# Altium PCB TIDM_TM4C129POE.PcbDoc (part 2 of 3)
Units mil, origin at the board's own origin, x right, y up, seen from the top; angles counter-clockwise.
Board outline 4950 x 3450 mil, 4 copper layers (Component Side, Ground Plane, Power Plane, Solder Side), stack 59.6 mil thick; 159 components, 154 nets, 570 pads, 297 vias.
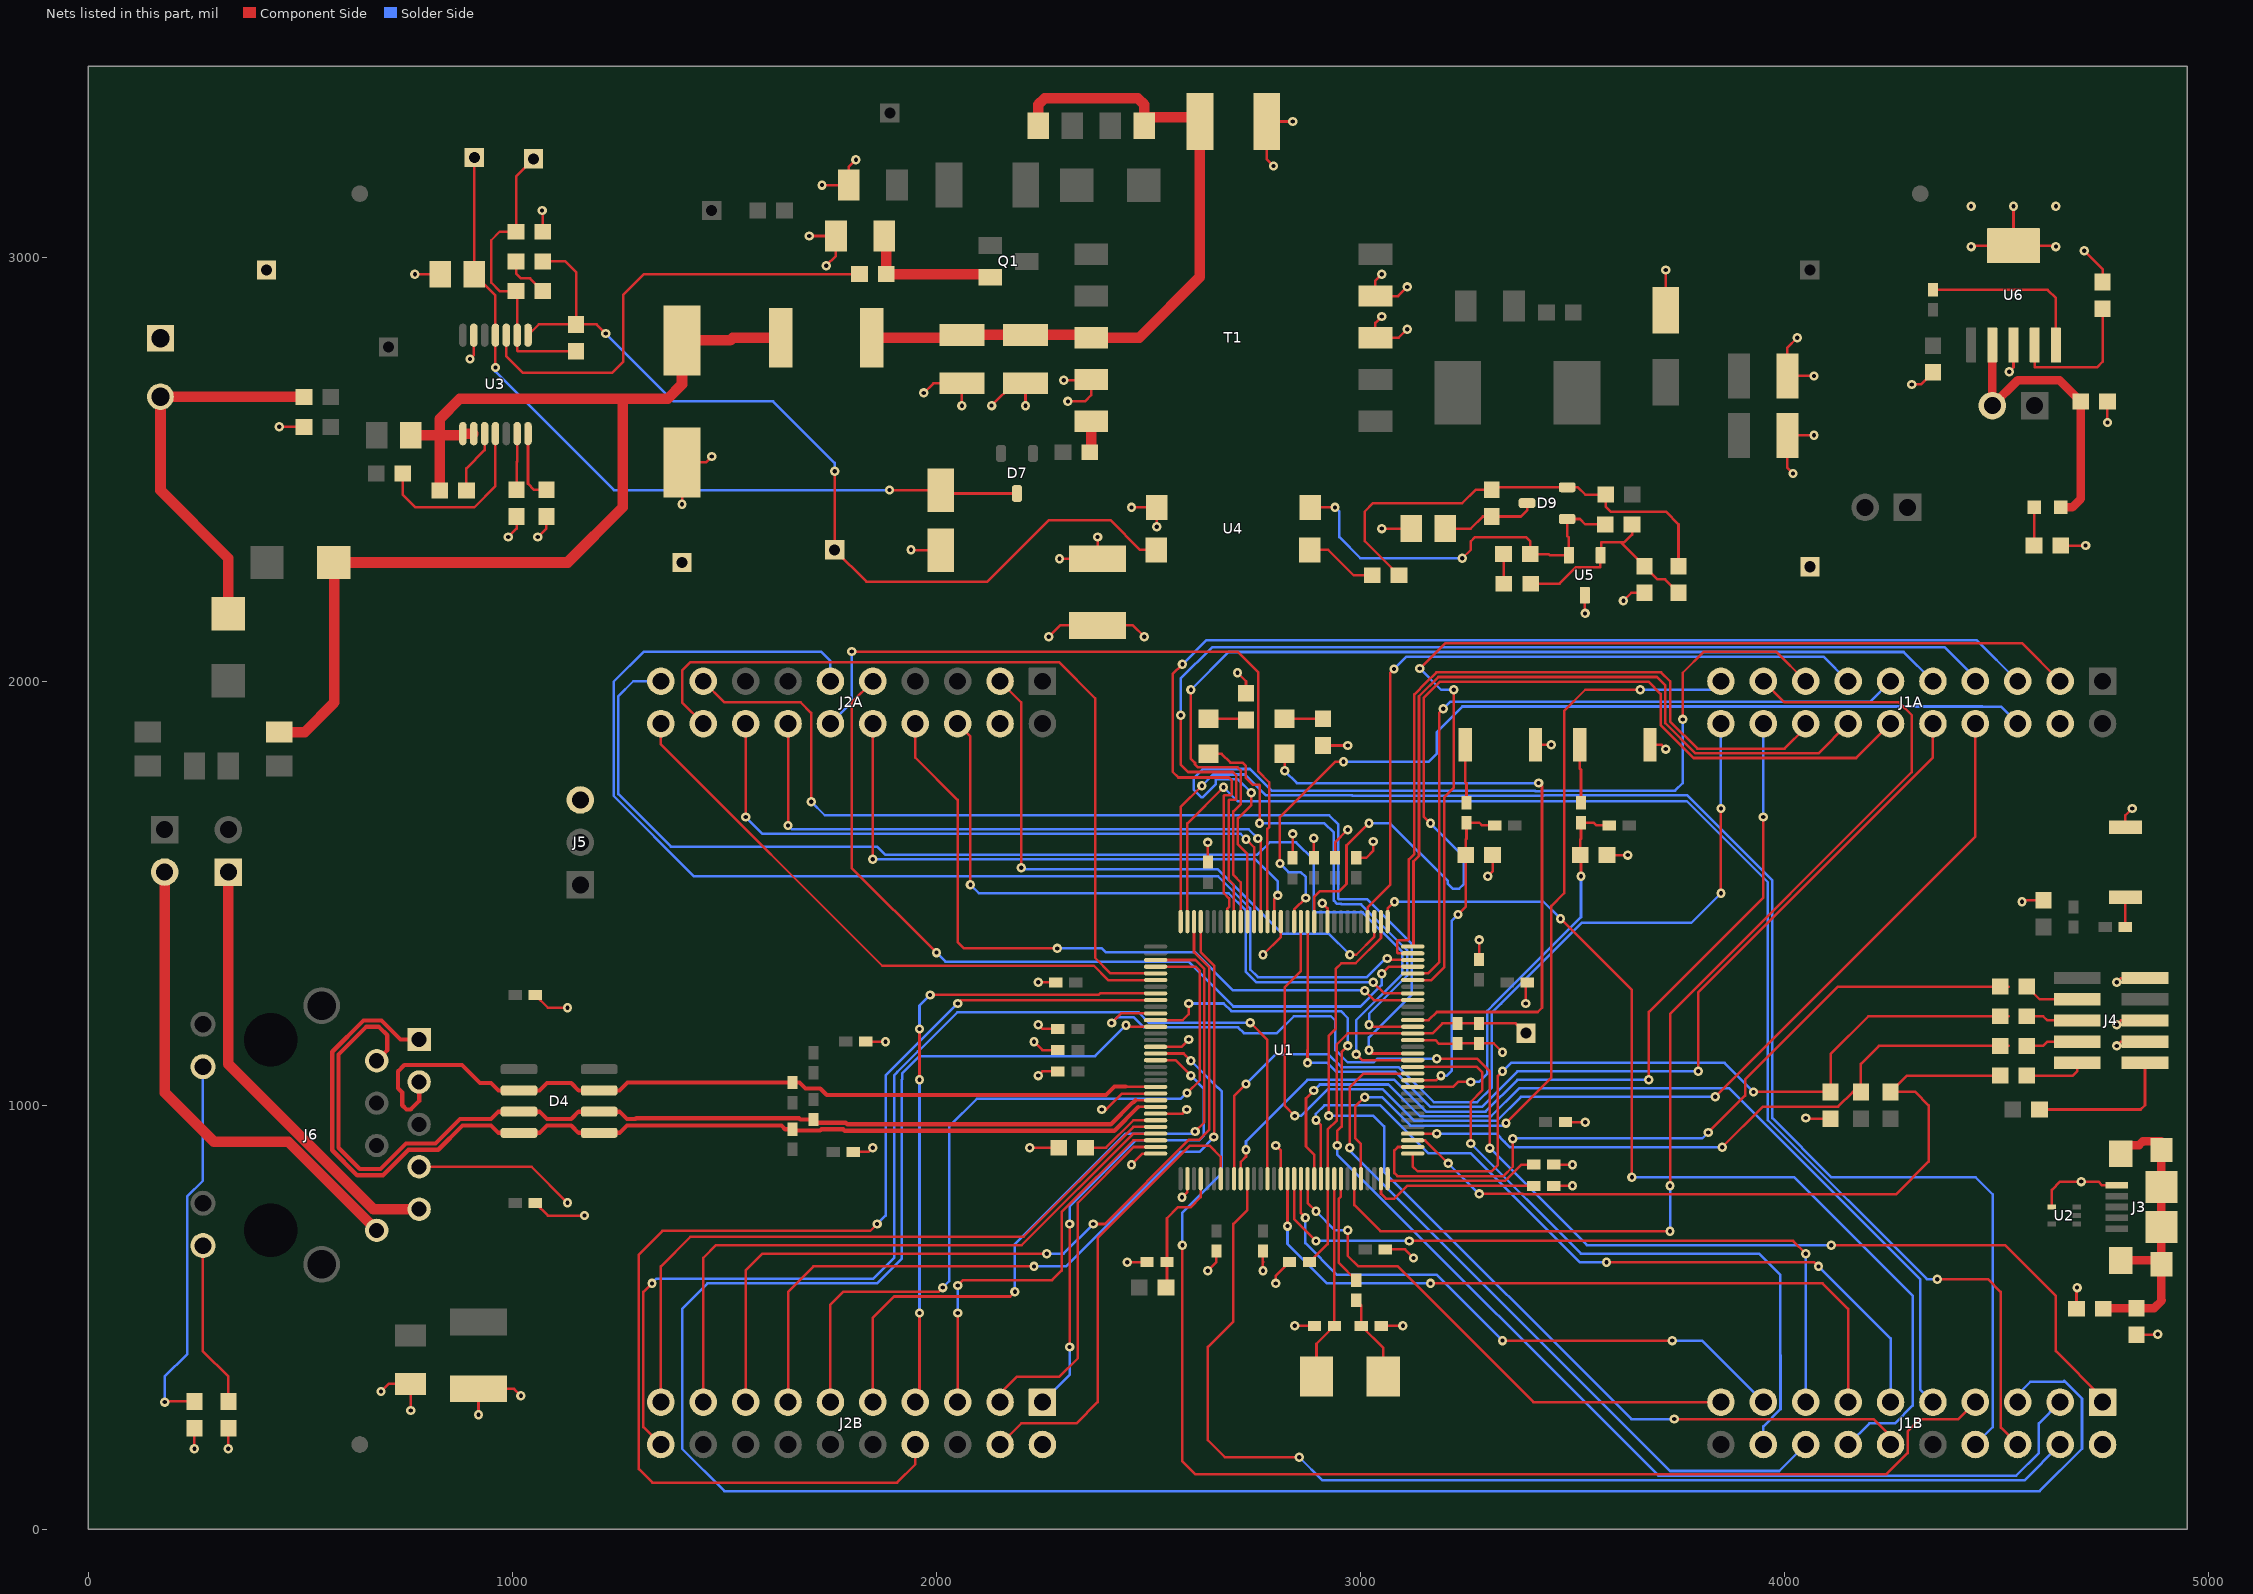
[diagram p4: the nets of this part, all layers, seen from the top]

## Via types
v1: diameter 22, hole 10, Component Side to Solder Side, 297 vias

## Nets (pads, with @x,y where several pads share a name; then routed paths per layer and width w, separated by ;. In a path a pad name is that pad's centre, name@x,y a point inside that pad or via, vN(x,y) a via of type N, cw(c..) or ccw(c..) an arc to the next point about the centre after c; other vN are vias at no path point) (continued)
EPHYRX_P: D4.2 D4.7 J6.3 R22.1 U1.54 | length 2042.3
  Component Side w6: 2446.21,1043.39 U1.54@2516.85,1043.39
  Component Side w10: J6.3@780,1055 780,1010 760,990 750,990 740,1000 740,1030 730,1040 730,1080 745,1095 881.29,1095 923.79,1052.5 949.7,1052.5 967.2,1035 D4.2@1015.51,1035 1063.82,1035 1081.32,1052.5 1138.68,1052.5 1156.18,1035 D4.7@1204.49,1035 1252.8,1035 1271.42,1053.62 R22.1@1660,1053.62 1676.81,1053.62 1691.06,1039.37 1725.96,1039.37 1741.33,1024 2399.81,1024 2420,1044.19 2446.21,1044.19
EPHYTX_N: D4.3 D4.6 J6.2 R23.1 U1.56 | length 2496.1
  Component Side w6: 2469.42,1011.89 U1.56@2516.85,1011.89
  Component Side w10: J6.2@680,1105 705,1130 705,1165 685,1185 655,1185 590,1120 590,900 640,850 688.79,850 748.79,910 818.79,910 876.29,967.5 949.7,967.5 967.2,985 D4.3@1015.51,985 1063.82,985 1081.32,967.5 1138.68,967.5 1156.18,985 D4.6@1204.49,985 1252.8,985 1270.3,967.5 1290,967.5 1291.87,969.37 1675.95,969.37 1678.95,966.38 R23.1@1710,966.38 1717.76,958.62 1786.21,958.62 1789.84,955 2411.16,955 2462.66,1006.5 2464.03,1006.5 2469.42,1011.89
EPHYTX_P: D4.4 D4.5 J6.1 R24.1 U1.57 | length 2558.8
  Component Side w6: 2475.64,996.14 U1.57@2516.85,996.14
  Component Side w10: J6.1@777.35,1155 736.21,1155 691.21,1200 648.79,1200 575,1126.21 575,893.79 633.79,835 695,835 755,895 825,895 882.5,952.5 949.7,952.5 967.2,935 D4.4@1015.51,935 1063.82,935 1081.32,952.5 1138.68,952.5 1156.18,935 D4.5@1204.49,935 1252.8,935 1270.3,952.5 1634.31,952.5 1643.19,943.62 R24.1@1660,943.62 1662.99,940.63 1725.96,940.63 1728.95,943.62 1780,943.62 1783.62,940 2419.49,940 2475.64,996.14
GND: C1.2 C2.2 C3.2 C4.2 C5.2 C6.2 C7.2 C8.2 C9.2 C10.2 C11.2 C12.2 C13.2 C14.2 C15.2 C16.2 C17.2 C18.2 C19.2 C20.2 C21.2 C22.2 C23.2 C24.2 C25.2 C26.2 C27.2 C28.2 C29.2 C30.1 C31.2 C43.1 C44.2 C45.2 C46.2 C47.2 C50.2 C51.2 C52.2 J1A.4 J1B.2 J2A.4 J2B.2 J3.5 J4.3 J4.5 J4.9 J5.3 J6.7 R3.1 R6.2 R7.2 R19.1 R20.1 R25.2 R27.2 R28.2 R29.1 R47.1 R50.1 R51.1 S1.1 S2.1 S3.1 T1.7 T1.8 TP5.1 U1.10 U1.17 U1.48 U1.55 U1.58 U1.64 U1.66 U1.80 U1.114 U2.4 U5.3 U6.3 U6.6 | length 6078.5
  Component Side w6: v1(250,190) R6.2@250,238.5 ; v1(330,190) R7.2@330,238.5 ; v1(690,325) 707.91,342.91 R29.1@760,342.91 v1(760,280) ; J6.7@780,855 1045,855 v1(1130,770) ; v1(920,270) C31.2@920,331.26 1003.74,331.26 v1(1020,315) ; C27.2@1053.62,770 1083.62,740 v1(1170,740) ; C26.2@1053.62,1260 1083.62,1230 v1(1130,1230) ; C29.2@1803.62,890 1840,890 v1(1850,900) ; C28.2@1833.62,1150 v1(1880,1150) ; v1(2220,900) R3.1@2288.5,900 ; v1(2230,1150) 2250,1130 C12.2@2286.38,1130 ; v1(2240,1070) 2250,1080 C3.2@2286.38,1080 ; v1(2240,1190) 2250,1180 C6.2@2286.38,1180 ; v1(2240,1290) C5.2@2281.38,1290 ; v1(2265,2105) 2291.58,2131.58 C43.1@2380,2131.58 2463.42,2131.58 v1(2490,2105) ; v1@2390,991 v1(2390,990) 2400,990 2437.64,1027.64 U1.55@2516.85,1027.64 ; v1(2450,630) C1.2@2496.4,630 ; v1(2460,860) 2485.91,885.91 U1.64@2516.85,885.91 ; U1.58@2516.85,980.39 2580.39,980.39 v1(2590,990) ; U1.48@2516.85,1137.87 2577.87,1137.87 v1(2595,1155) ; v1(2579.15,783.29) 2591.65,795.79 U1.66@2591.65,826.85 ; v1(2640,610) 2660,630 C9.2@2660,656.38 ; C11.2@2640,1573.62 v1(2640,1620) ; v1(2710,2020) 2730,2000 R27.2@2730,1971.5 ; v1(2770,610) 2770,631 ; C10.2@2770,656.38 2770,631 ; v1(2770,1355) 2812.13,1397.13 U1.17@2812.13,1433.15 ; 2771,630 2770,631 ; v1(2795,3215) 2778.74,3231.26 C30.1@2778.74,3320 v1(2840,3320) ; v1(2800,580) 2800,597.38 C19.2@2832.62,630 C19.2@2837,630 ; v1(2800,905) 2812.13,892.87 U1.80@2812.13,826.85 ; C15.2@2840,1583 C15.2@2840,1583.62 v1(2840,1640) ; v1(2845,480) C20.2@2891.38,480 ; C16.2@2890,1583 C16.2@2890,1583.62 v1(2890,1630) ; v1(2909.86,1476.71) 2922.36,1464.21 U1.10@2922.36,1433.15 ; R28.2@2911.3,1848.5 v1(2970,1848.5) ; C4.2@2940,1583 C4.2@2940,1583.62 2940,1620 v1(2970,1650) ; C2.2@2990,1583.62 3013.62,1583.62 3030,1600 v1(3030,1622) ; C21.2@3048.62,480 v1(3100,480) ; v1(3050,2360) C47.2@3119.68,2360 ; v1(3050,2860) 3035,2845 T1.8@3035,2810 3090,2810 v1(3110,2830) ; v1(3050,2960) 3035,2945 T1.7@3035,2908.43 3088.43,2908.43 v1(3110,2930) ; C8.2@3058.62,660 3105,660 v1(3125,640) ; U1.114@3123.15,1153.62 3176.38,1153.62 3185,1145 3228.22,1145 C17.2@3228.97,1145.75 ; C17.2@3229,1145.78 C18.2@3279,1145.78 3314.22,1145.78 v1(3335,1125) ; C7.2@3280,1340 C7.2@3280,1343.62 v1(3280,1390) ; v1(3300,1540) 3311.5,1551.5 C24.2@3311.5,1590 ; v1(3390,1240) 3390,1286.38 C14.2@3393.62,1290 C14.2@3390,1290 ; S3.1@3412.68,1850 v1(3450,1850) ; R50.1@3453,810 R50.1@3455.43,810 v1(3500,810) ; R51.1@3453,860 R51.1@3455.43,860 v1(3500,860) ; C13.2@3483.62,960 v1(3530,960) ; U5.3@3528.93,2202.76 3528.93,2160.75 v1(3529.68,2160) ; C23.2@3581.5,1590 v1(3630,1590) ; v1(3620,2190) 3638.5,2208.5 R47.1@3670,2208.5 ; S2.1@3682.68,1850 3710,1850 v1(3720,1840) ; C44.2@3719.68,2874.65 v1(3719.68,2970) ; v1(4020,2490) 4006.77,2503.23 C46.2@4006.77,2580 v1(4069.68,2580) ; v1(4030,2810) 4006.77,2786.77 C45.2@4006.77,2720 v1(4069.68,2720) ; v1(4050,970) 4051.5,968.5 R19.1@4108.7,968.5 ; v1(4300,2700) 4321.5,2700 C50.2@4350,2728.5 ; v1(4440,3025) 4442.13,3027.13 U6.6@4540,3027.13 ; v1(4530,2730) 4540,2740 U6.3@4540,2792.87 ; v1(4540,3120) U6.6@4540,3027.13 ; v1(4560,1480) 4563.5,1483.5 C22.2@4611,1483.5 ; U2.4@4630.47,759.68 4630.47,800.47 4650,820 v1(4700,820) 4740,820 4748.82,811.18 J3.5@4783.66,811.18 ; v1(4640,3025) 4637.87,3027.13 U6.6@4540,3027.13 ; R25.2@4651.5,2320 v1(4710,2320) ; R20.1@4688.5,520 4688.5,568.5 v1(4690,570) ; v1(4707,3015) 4750,2972 C51.2@4750,2941.5 ; v1(4761.5,2610) C52.2@4761.5,2660 ; v1(4783.53,1140) 4793.53,1150 J4.3@4850.12,1150 ; v1(4783.53,1190) 4793.53,1200 J4.5@4850.12,1200 ; v1(4783.53,1290) 4793.53,1300 J4.9@4850.12,1300 ; S1.1@4804,1655.68 4804,1684 v1(4820,1700) ; C25.2@4830,458.5 4878.5,458.5 v1(4880,460)
  other v1: 4440,3120 4640,3120
GNDX: C34.2 C36.2 C37.2 C38.2 C40.2 C41.2 C42.2 C43.2 J7.1 R30.1 R32.1 R33.1 R40.2 T1.2 TP2.1 TP7.1 U3.6 U4.3 | length 1576.4
  Component Side w6: v1(450,2600) R30.1@508.5,2600 ; v1(770,2960) C38.2@830,2960 ; v1(900,2760) 908.82,2768.82 U3.6@908.82,2816.14 ; v1(990,2340) 1010,2360 R33.1@1010,2388.5 R33.1@1010,2389 ; v1(1060,2340) 1080,2360 R32.1@1080,2388.5 ; v1(1070,3110) 1071.5,3108.5 C34.2@1071.5,3060 ; v1(1400,2417.62) C42.2@1400,2516.3 1456.3,2516.3 v1(1470,2530) ; v1(1700,3050) R40.2@1762.91,3050 1762.91,3002.91 v1(1740,2980) ; v1(1730,3170) C36.2@1792.91,3170 1792.91,3212.91 v1(1810,3230) ; v1(1940,2310) 1940.87,2309.13 C37.2@2010,2309.13 ; v1(1970,2680) 1992.6,2702.6 C40.2@2060,2702.6 v1(2060,2649.69) ; v1(2130,2650) 2182.6,2702.6 C41.2@2210,2702.6 v1(2210,2649.69) ; v1(2290,2289.06) C43.2@2380,2289.06 v1(2380,2340) ; v1(2300,2710) 2363.43,2710 T1.2@2365,2711.57 2365,2675 2350,2660 v1(2310,2660) ; v1(2460,2410) U4.3@2519.39,2410 v1(2519.39,2364.47)
GPIOSW1: C23.1 R8.1 R9.1 U1.107 | length 942.1
  Component Side w6: U1.107@3123.15,1043.39 3218.39,1043.39 3230,1055 v1(3260,1055) ; v1(3520,1540) 3520,1588.5 C23.1@3518.5,1590 3518.5,1627 3520,1628.5 R8.1@3520,1666.38 3550,1666.38 3556.38,1660 R9.1@3586.38,1660
  Solder Side w6: v1(3260,1055) 3279,1055 3299,1075 3299,1222.9 3321.1,1245 3520,1443.9 v1(3520,1540)
GPIOSW2: C24.1 R10.1 R11.1 U1.108 | length 769.7
  Component Side w6: U1.108@3123.15,1059.13 3179.13,1059.13 v1(3190,1070) ; v1(3230,1450) 3248.5,1468.5 C24.1@3248.5,1590 3248.5,1627 3250,1628.5 R10.1@3250,1666.38 3280,1666.38 3286.38,1660 R11.1@3316.38,1660
  Solder Side w6: v1(3190,1070) 3203.78,1070 3215,1081.22 3215,1435 v1(3230,1450)
GPLED0: D1.2 U1.116 | length 1142
  Component Side w6: D1.2@2641.3,1828.66 2672.31,1828.66 2693,1807.97 2721.97,1807.97 2728.94,1801 2728.94,1772.56 2745.5,1756 2761,1756 2762,1755 v1(2762,1665) ; v1(3020,1190) 3024.88,1185.12 U1.116@3123.15,1185.12
  Solder Side w6: v1(2762,1665) 2915,1665 2937,1643 2937,1482.44 2944.44,1475 2954.14,1475 2955.14,1474 3001.6,1474 3110,1365.6 3110,1305.44 3020.59,1216.03 3020.59,1190.59 v1(3020,1190)
GPLED1: D2.2 U1.117 | length 1500.8
  Component Side w6: v1(2821.3,1788.7) D2.2@2821.3,1828.66 ; U1.117@3123.15,1200.87 3160.87,1200.87 3180,1220 3418,1220 3428,1230 3428,1752 v1(3420,1760)
  Solder Side w6: v1(2821.3,1788.7) 2850.06,1759.94 3419.94,1759.94 v1(3420,1760)
JTAG_TCK: R14.2 R18.1 U1.100 | length 1556.9
  Component Side w6: U1.100@3123.15,933.15 v1(3180,933.15) ; v1(3853,901) 3949,997 4126.5,997 4161,1031.5 R18.1@4180,1031.5 4180,1097.5 4222.5,1140 4528.5,1140
  Solder Side w6: v1(3180,933.15) 3320.59,933.15 3340,913.74 3340,913.13 3351.13,902 3351.74,902 3352.94,900.8 3852.8,900.8 v1(3853,901)
JTAG_TDI: R16.2 U1.98 | length 1797.3
  Component Side w6: U1.98@3123.15,901.65 3088,901.65 3080,893.65 3080,840 3087,833 3337,833 3359,855 v1(3359,921) ; v1(3820,936) 3907,1023 3907,1060.5 4126.5,1280 4528.5,1280
  Solder Side w6: v1(3359,921) 3360,922 3804,922 3806,922 v1(3820,936)
JTAG_TDO: R15.2 R19.2 U1.97 | length 1824
  Component Side w6: U1.97@3123.15,885.91 3123.15,855.81 3134.96,844 3309,844 3324,859 3324,1069 v1(3335,1080) ; v1(3927,1031.5) R19.2@4108.7,1031.5 4108.7,1120.7 4198,1210 4528.5,1210
  Solder Side w6: v1(3335,1080) 3355,1100 3858.5,1100 v1(3927,1031.5)
JTAG_TMS: R13.2 R17.1 U1.99 | length 1812
  Component Side w6: U1.99@3123.15,917.4 3152.6,917.4 v1(3207,863) ; v1(3280,791) 3383,791 3384,790 4263,790 4340,867 4340,1000 4308.5,1031.5 R17.1@4250,1031.5 4288.5,1070 R13.2@4508.5,1070
  Solder Side w6: v1(3207,863) 3279,791 v1(3280,791)
NetC1_1: C1.1 R1.2 U1.68 | length 308.2
  Component Side w6: R1.2@2541.5,570 2543.64,572.14 C1.1@2543.64,630 2543.64,733.64 2570,760 2600,760 2623.15,783.15 U1.68@2623.15,826.85
NetC17_1: C17.1 C18.1 C19.1 TP1.1 U1.87 U1.115 | length 1016.5
  Component Side w6: C19.1@2879.86,630 2922.36,672.5 U1.87@2922.36,826.85 2922.36,942.36 2944.5,964.5 2944.5,1143.87 2970,1169.37 U1.115@3123.15,1169.37 3169.37,1169.37 3192.99,1192.99 C17.1@3228.97,1192.99 C18.1@3279,1193.02 ; C18.1@3279,1193.02 3365.78,1193.02 3389.4,1169.4 TP1.1@3390,1170
NetC20_1: C20.1 U1.88 Y1.2 | length 515
  Component Side w6: Y1.2@2896.26,330 Y1.2@2896.26,360 2896.26,437.64 C20.1@2938.62,480 2938.11,480.51 2938.11,785.07 2938.62,785.58 2938.62,826.34 U1.88@2938.11,826.85
NetC21_1: C21.1 R2.2 Y1.1 | length 236.4
  Component Side w6: R2.2@2990,540 3001.38,528.62 C21.1@3001.38,480 3053.74,427.64 Y1.1@3053.74,360 Y1.1@3053.74,330
NetC25_1: C25.1 J3.6 J3.7 J3.8 J3.9 J3.10 J3.11 R20.2 | length 683.2
  Component Side w20: R20.2@4750,521.5 C25.1@4830,521.5 4871.5,521.5 4890,540 4888.98,541.02 J3.8@4888.98,625.16 4880.12,634.02 J3.6@4792.52,634.02 ; J3.7@4792.52,905.98 4836,905.98 4844.86,914.84 4888.98,914.84 J3.11@4888.98,894.84 J3.10@4888.98,827.24 ; J3.8@4888.98,645.16 J3.9@4888.98,712.76 J3.10@4888.98,807.24
NetC34_1: C34.1 R36.2 R37.2 TP9.1 U3.2 | length 703.3
  Component Side w6: TP9.1@1050,3232 1008.5,3190.5 C34.1@1008.5,3060 970,3060 950,3040 950,2940 970,2920 R36.2@1008.5,2920 1011.18,2917.32 U3.2@1011.18,2816.14 1011.18,2780 1012.68,2778.5 R37.2@1150,2778.5
NetC35_1: C35.1 R36.1 | length 108.7
  Component Side w6: C35.1@1008.5,2990 1008.5,2961.5 1020,2950 1041.5,2950 R36.1@1071.5,2920
NetC35_2: C35.2 R37.1 TP11.1 U3.1 U4.4 | length 2164.9
  Component Side w6: U3.1@1036.77,2816.14 1062.13,2841.5 R37.1@1150,2841.5 ; C35.2@1071.5,2990 1125,2990 1150,2965 R37.1@1150,2841.5 ; v1(1220,2820) 1198.5,2841.5 R37.1@1150,2841.5 ; v1(1760,2495) TP11.1@1760,2310 1835,2235 2120,2235 2265,2380 2410,2380 2480,2310 U4.4@2518.41,2310
  Solder Side w6: v1(1220,2820) 1380,2660 1615,2660 1760,2515 v1(1760,2495)
NetC37_1: C37.1 C38.1 D7.3 TP6.1 U3.4 | length 1874.7
  Component Side w6: TP6.1@910,3235 C38.1@910,2960 960,2910 U3.4@960,2816.14 v1(960,2740) ; v1(1889.13,2450.87) C37.1@2010,2450.87 2018.11,2442.76 D7.3@2190,2442.76
  Solder Side w6: v1(960,2740) 960,2730 1239.13,2450.87 v1(1889.13,2450.87)
NetC47_1: C47.1 D9.3 R45.1 | length 228
  Component Side w6: C47.1@3199.68,2360 3260,2360 3288.5,2388.5 R45.1@3309.68,2388.5 3378.5,2388.5 3392.76,2402.76 D9.3@3392.76,2420
NetC48_1: C48.1 C49.1 R47.2 R48.1 U5.1 | length 530.8
  Component Side w6: C49.1@3401.18,2230 3469.68,2230 3508.68,2269 3565.34,2269 U5.1@3566.34,2297.24 3567.34,2328 3613.5,2328 ; C48.1@3640.43,2370 3640.43,2346 3622.43,2328 3613.5,2328 ; R48.1@3750,2208.5 3718.5,2240 3700,2240 3670,2270 R47.2@3670,2271.5 3613.5,2328
NetC48_2: C48.2 D9.1 R49.1 U4.2 U5.2 | length 944.8
  Component Side w6: U4.2@2881.59,2410 v1(2940,2410) ; v1(3240,2290) 3260,2310 3260,2330 3270,2340 3390,2340 3400.43,2329.57 R49.1@3400.43,2300 3443.68,2300 3446.44,2297.24 U5.2@3491.53,2297.24 3491.53,2338.47 3487.24,2342.76 D9.1@3487.24,2382.6 3517.4,2382.6 3530,2370 C48.2@3577.44,2370
  Solder Side w6: v1(2940,2410) 2950,2400 2950,2340 3000,2290 v1(3240,2290)
NetC49_2: C49.2 R49.2 | length 70.3
  Component Side w6: R49.2@3337.44,2300 3337.44,2230.75 C49.2@3338.19,2230
NetC51_1: C51.1 U6.4 | length 342.9
  Component Side w6: U6.4@4590,2792.87 4590,2741 4591,2740 4736.5,2740 4750,2753.5 C51.1@4750,2878.5
NetC52_1: C52.1 D3.2 J9.2 U6.2 | length 682.2
  Component Side w20: U6.2@4490,2792.87 J9.2@4490,2650 4550,2710 4648.5,2710 C52.1@4698.5,2660 4698.5,2430 4678.5,2410 D3.2@4651.5,2410
NetD1_1: D1.1 R27.1 | length 90.1
  Component Side w6: D1.1@2641.3,1911.34 2730,1911.34 2731.14,1911.34 R27.1@2731.3,1911.5
NetD2_1: D2.1 R28.1 | length 90.1
  Component Side w6: D2.1@2821.3,1911.34 2866,1911.34 2866.16,1911.5 R28.1@2911.3,1911.5
NetD3_1: D3.1 R25.1 | length 90
  Component Side w6: R25.1@4588.5,2320 D3.1@4588.5,2410
NetD9_2: D9.2 R44.1 R45.2 R46.2 R48.2 | length 1098.4
  Component Side w6: R46.2@3090.75,2250 3010,2330.75 3010,2400 3030,2420 3240,2420 3271.5,2451.5 R45.2@3309.68,2451.5 3315.59,2457.4 D9.2@3487.24,2457.4 3512.6,2457.4 3530,2440 R44.1@3578.19,2440 3578.19,2411.81 3590,2400 3720,2400 3750,2370 R48.2@3750,2271.5
NetJ4_1: J4.1 R12.2 | length 352.7
  Component Side w6: R12.2@4601.5,990 4840,990 4850.12,1000.12 J4.1@4850.12,1100
NetJ4_2: J4.2 R13.1 | length 142.7
  Component Side w6: R13.1@4571.5,1070 4680,1070 4690,1080 4690,1099.88 J4.2@4689.88,1100
NetJ4_4: J4.4 R14.1 | length 122.5
  Component Side w6: R14.1@4571.5,1140 4610,1140 4620,1150 J4.4@4689.88,1150
NetJ4_6: J4.6 R15.1 | length 177.9
  Component Side w6: R15.1@4571.5,1210 4610,1210 4620,1200 J4.6@4642,1200 ; J4.6@4689.88,1200 J4.6@4642,1200 ; J4.6@4693.23,1190 4652,1190 J4.6@4642,1200
NetJ4_8: J4.8 R16.1 | length 130.8
  Component Side w6: R16.1@4571.5,1280 4601.5,1250 J4.8@4689.88,1250
NetJ6_12: J6.12 R6.1 | length 899
  Component Side w6: v1(180,300) 181.5,301.5 R6.1@250,301.5
  Solder Side w6: v1(180,300) 180,360 232.63,412.63 232.63,784.52 270.16,822.05 J6.12@270.16,1091.02
NetJ6_14: J6.14 R7.1 | length 392.3
  Component Side w6: J6.14@270.16,668.98 270.16,419.84 330,360 R7.1@330,301.5
NetR2_1: R2.1 U1.89 | length 258.5
  Component Side w6: U1.89@2953.86,826.85 2953.86,784.75 2949.11,780 2949.11,628.13 R2.1@2990,587.24
NetR3_2: R3.2 U1.59 | length 192.1
  Component Side w6: R3.2@2351.5,900 2400,900 2464.65,964.65 U1.59@2516.85,964.65
NetR4_2: R4.2 S1.2 | length 70.5
  Component Side w6: R4.2@4803.62,1420 4804,1420.38 S1.2@4804,1490.32
NetR8_2: R8.2 S2.2 | length 137.5
  Component Side w6: S2.2@3517.32,1850 3517.32,1793.85 3520,1791.17 R8.2@3520,1713.62
NetR10_2: R10.2 S3.2 | length 137.5
  Component Side w6: S3.2@3247.32,1850 3247.32,1761.68 3250,1759 R10.2@3250,1713.62
NetR26_2: R26.2 U6.5 | length 409.3
  Component Side w6: R26.2@4350,2923.62 4350,2923 4620.5,2923 4640,2903.5 U6.5@4640,2792.87
NetR32_2: R32.2 U3.14 | length 167.1
  Component Side w6: U3.14@1036.77,2583.86 1036.77,2466 1051.28,2451.5 R32.2@1080,2451.5
NetR33_2: R33.2 U3.13 | length 132.9
  Component Side w6: R33.2@1010,2451.5 1010,2517 1011.18,2518.18 U3.13@1011.18,2583.86
NetR34_2: R34.2 U3.11 | length 425.8
  Component Side w6: R34.2@741.5,2490 741.5,2439.5 771,2410 910,2410 960,2460 U3.11@960,2583.86
NetR35_1: R35.1 U3.10 | length 151.6
  Component Side w6: R35.1@891.5,2450 891.5,2502 934.41,2544.91 U3.10@934.41,2583.86
NetR39_1: R39.1 U3.3 | length 1088.3
  Component Side w6: U3.3@985.59,2816.14 985.59,2766 1024.6,2726.99 1234.93,2726.99 1260.89,2752.95 1260.89,2910.89 1310,2960 R39.1@1818.5,2960
NetR46_1: R46.1 U4.1 | length 172
  Component Side w6: U4.1@2880.61,2310 2924,2310 2984,2250 R46.1@3027.75,2250
NetR50_2: R50.2 U1.95 | length 412.3
  Component Side w6: U1.95@3048.35,826.85 3048.35,791.65 3060,780 3080,780 3110,810 3240,810 R50.2@3408.19,810
NetR51_2: R51.2 U1.96 | length 364.7
  Component Side w6: U1.96@3064.09,826.85 3064.09,822 3341.56,822 3346.41,826.85 3347.01,826.85 3380.16,860 R51.2@3408.19,860
PA2: J2B.9 U1.35 | length 1723
  Component Side w6: J2B.9@1850,300 1850,499 1900,549 2174,549 v1(2185,560) ; U1.35@2516.85,1342.6 2610.49,1342.6 2632,1321.09 2632,960 v1(2610,938)
  Solder Side w6: v1(2185,560) 2185,672.5 2445.5,933 2605,933 v1(2610,938)
PA3: J2B.11 U1.36 | length 1901.3
  Component Side w6: J2B.11@1750,300 1750,530 1780,560 2005,560 v1(2015,570) ; U1.36@2516.85,1326.85 2610.68,1326.85 2621,1316.53 2621,1059 v1(2591,1029)
  Solder Side w6: v1(2015,570) 2030,585 2030,950 2095,1015 2576,1015 2591,1030 v1(2591,1029)
PA4: J2A.18 U1.37 | length 1933.3
  Component Side w6: J2A.18@1450,1900 1400,1950 1400,2025 1420,2045 2289,2045 2374.5,1959.5 2374.5,1347.5 2410.9,1311.1 U1.37@2516.85,1311.1
PA5: J2A.20 U1.38 | length 1445.9
  Component Side w6: J2A.20@1350,1900 1350,1851.11 1872.11,1329 2371,1329 2404.65,1295.35 U1.38@2516.85,1295.35
PA6: J2B.7 U1.40 | length 1507.9
  Component Side w6: J2B.7@1950,300 1960,310 v1(1960,510) ; v1(1960,1060) v1(1960,1180) ; v1(1985,1260) 1985.61,1260.61 2382.87,1260.61 2386.12,1263.86 U1.40@2516.85,1263.86
  Solder Side w6: v1(1960,510) v1(1960,1060) ; v1(1960,1180) 1960,1235 v1(1985,1260)
PA7: J2B.8 U1.41 | length 2896.8
  Component Side w6: v1(1860,720) 1843.82,703.82 1353.82,703.82 1298,648 1298,142 1330,110 1907,110 1950,153 J2B.8@1950,200 ; v1(2050,1240) 2058.11,1248.11 U1.41@2516.85,1248.11
  Solder Side w6: v1(1860,720) 1880,740 1880,1070 v1(2050,1240)
PB2: J1A.17 U1.91 | length 2668.6
  Component Side w6: U1.91@2985.35,826.85 2985.35,764.65 3047,703 v1(3730,703) ; v1(3730,810) 3730,1215.56 4300,1785.56 4300,1920 4270,1950 4000,1950 J1A.17@3950,2000
  Solder Side w6: v1(3730,703) v1(3730,810)
PB3: J1A.19 U1.92 | length 1999.5
  Component Side w6: U1.92@3001.1,826.85 3001.1,908.9 2988,922 2988,998 3010,1020 v1(3010,1019) ; v1(3343,958) 3450,1065 3450,1470 3480,1500 3480,1930 3530,1980 v1(3660,1980)
  Solder Side w6: v1(3010,1019) 3051,1019 3117.85,952.15 3337.15,952.15 v1(3343,958) ; v1(3660,1980) 3830,1980 J1A.19@3850,2000
PB4: J2A.6 U1.121 | length 1626.4
  Component Side w6: J2A.6@2050,1900 2080,1870 v1(2080,1520) ; v1(3030,1290) 3056.14,1263.86 U1.121@3123.15,1263.86
  Solder Side w6: v1(2080,1520) 2100,1500 2689,1500 2729,1460 2729,1315.44 2754.44,1290 v1(3030,1290)
PB5: J2A.8 U1.120 | length 1686.3
  Component Side w6: J2A.8@1950,1900 1950,1820 2050,1720 2050,1385 2065,1370 v1(2285,1370) ; v1(3010,1270) 3031.89,1248.11 U1.120@3123.15,1248.11
  Solder Side w6: v1(2285,1370) 2390,1370 2399,1361 2609.2,1361 2699.2,1271 3009,1271 v1(3010,1270)
PC4: J1A.5 U1.25 | length 2800.5
  Component Side w6: v1(2580,2040) 2557,2017 2557,1786.5 2570.5,1773 2689.94,1773 2695.94,1767 2695.94,1733 2694,1731.06 2679,1731.06 2678,1730.06 2678,1500 2690,1488 2690,1467.86 2686.14,1464 U1.25@2686.14,1433.15
  Solder Side w6: v1(2580,2040) 2637,2097 4453,2097 J1A.5@4550,2000
PC5: J1A.7 U1.24 | length 2652.9
  Component Side w6: v1(2576,1919.62) 2576,1803.5 2593.53,1785.97 2698.97,1785.97 2706.94,1778 2706.94,1722 2705,1720.06 2690,1720.06 2689,1719.06 2689,1532.45 2701.07,1520.38 2701.07,1456.82 2701.89,1456 U1.24@2701.89,1433.15
  Solder Side w6: v1(2576,1919.62) 2576,2006 2650,2080 4378,2080 4450,2008 J1A.7@4450,2000
PC6: J1A.9 U1.23 | length 2480.7
  Component Side w6: v1(2600,1980) 2600,1816.97 2609.68,1807.29 2609.68,1803.69 2616.4,1796.97 2709.97,1796.97 2717.94,1789 2717.94,1711 2700,1693.06 2700,1543.45 2717.64,1525.81 U1.23@2717.64,1433.15
  Solder Side w6: v1(2600,1980) 2689,2069 4281,2069 J1A.9@4350,2000
PC7: J1A.15 U1.22 | length 2324.8
  Component Side w6: U1.22@2733.39,1433.15 2733.39,1592.76 2711,1615.15 2711,1676.68 2742.5,1708.18 v1(2742.5,1737) ; v1(3760,1910) 3760,2020 3810,2070 3980,2070 J1A.15@4050,2000
  Solder Side w6: v1(2742.5,1737) 2710.44,1769.06 2660,1769.06 2658.96,1768.03 2658.96,1758.01 2626.95,1726 2624.95,1726 2607,1743.95 2607,1771.79 2628.21,1793 2739.42,1793 2790.42,1742 3411.13,1742 3412.13,1741 3427.87,1741 3428.87,1742 3742,1742 3760,1760 v1(3760,1910)
PD0: J1B.14 U1.1 | length 2368
  Component Side w6: U1.1@3064.09,1433.15 3064.09,1464.09 v1(3080,1480) ; v1(3471.5,1440) 3640,1271.5 v1(3640,830)
  Solder Side w6: v1(3080,1480) 3431.5,1480 v1(3471.5,1440) ; v1(3640,830) 4023,830 4302,551 4302,292 4260,250 4200,250 J1B.14@4150,200
PD1: J1B.12 U1.2 | length 2249.5
  Component Side w6: v1(2925,975) 2925,1163.78 2941.22,1180 2941.22,1321.22 2955,1335 2988.35,1335 3048.35,1395 U1.2@3048.35,1433.15 ; v1(3740,260) 3832.75,260 3833.23,259.52 4166.77,259.52 4167.25,260 4210,260 4250,220 J1B.12@4250,200
  Solder Side w6: v1(2925,975) 3030.5,975 3055.5,950 3055.5,843.11 3638.61,260 v1(3740,260)
PD2: J2A.3 U1.3 | length 1431.4
  Component Side w6: J2A.3@2150,2000 2200,1950 v1(2200,1560) ; v1(2975,1355) 2990,1355 3032.6,1397.6 U1.3@3032.6,1433.15
  Solder Side w6: v1(2200,1560) 2203,1557 2663.11,1557 2815.11,1405 2925,1405 v1(2975,1355)
PD3: J1A.13 U1.4 | length 1728.6
  Component Side w6: U1.4@3016.85,1433.15 3016.85,1466.85 3070,1520 3070,2020 v1(3079,2029)
  Solder Side w6: v1(3079,2029) 3108,2058 4092,2058 J1A.13@4150,2000
PD4: J2A.9 U1.125 | length 1974
  Component Side w6: J2A.9@1850,2000 1800,1950 1800,1560 v1(2000,1360) ; v1(3050,1310) 3066.85,1326.85 U1.125@3123.15,1326.85
  Solder Side w6: v1(2000,1360) 2021,1339 2560,1339 2581,1339 2594,1339 2700,1233 3000,1233 3000,1233.13 3050,1283.13 v1(3050,1310)
PD5: J2A.11 U1.126 | length 3033.8
  Component Side w6: v1(3063,1346) 3063,1344 3064,1343 3112.6,1343 3113,1342.6 U1.126@3123.15,1342.6
  Solder Side w6: J2A.11@1750,2000 1750,2048 1728,2070 1310,2070 1239,1999 1239,1729.44 1428.44,1540 2664.56,1540 2740,1464.56 2740,1350 2740,1345.56 2740,1320 2758,1302 3015.13,1302 3059.13,1346 v1(3063,1346)
PD6: J1A.16 U1.127 | length 1780.7
  Component Side w6: U1.127@3123.15,1358.35 3088,1358.35 3087,1359.35 3087,1388 3088,1389 3111,1389 3114,1392 3114,1580 3114.44,1580 3127,1592.56 3127,1969.11 3155,1997.11 3178.89,2021 3709,2021 3730,2000 3730,1905.56 3794.56,1841 4000,1841 4050,1891 J1A.16@4050,1900
PD7: J1A.14 U1.128 | length 1784.2
  Component Side w6: U1.128@3123.15,1374.09 3125,1374.09 3125,1575 3138,1588 3138,1964.56 3183.44,2010 3699,2010 3719,1990 3719,1901 3790,1830 4080,1830 J1A.14@4150,1900
PE0: J1A.6 U1.15 | length 2194.4
  Component Side w6: v1(2810,1570) 2810,1680 2940,1810 v1(2960,1810) ; U1.15@2843.62,1433.15 2843.62,1461.62 v1(2871,1489)
  Solder Side w6: v1(2810,1570) 2830,1550 2859,1550 2871,1538 v1(2871,1489) ; v1(2960,1810) 3160,1810 3180,1830 3180,1880 3240.48,1940.48 4466.77,1940.48 4467.25,1940 4510,1940 J1A.6@4550,1900
PE1: J1A.8 U1.14 | length 2689.8
  Component Side w6: v1(2845,975) 2821.5,998.5 2821.5,1278.5 2859.37,1316.37 U1.14@2859.37,1433.15 ; v1(3836.48,1020) 4450,1633.52 J1A.8@4450,1900
  Solder Side w6: v1(2845,975) 2860,975 2923,1038 3052,1038 3126.85,963.15 3321.28,963.15 3378.13,1020 v1(3836.48,1020)
PE2: J1A.10 U1.13 | length 2381.7
  Component Side w6: v1(2875,1100) 2875,1129.88 2875.12,1130 U1.13@2875.12,1433.15 ; v1(3796.46,1080) 3796.46,1266.46 4350,1820 J1A.10@4350,1900
  Solder Side w6: v1(2875,1100) 2922,1100 2943,1079 3082.15,1079 3165,996.15 3286.15,996.15 3370,1080 v1(3796.46,1080)
PE3: J1A.12 U1.12 | length 2354.4
  Component Side w6: U1.12@2890.87,1433.15 2890.86,1457.71 2890.86,1491 2904.87,1505 2950,1505 2967,1522 2967,1613 3019,1665 v1(3020,1665) ; v1(3165,1665) 3149,1681 3149,1960 3188,1999 3679,1999 3708,1970 3708,1896.44 3785.44,1819 4169,1819 J1A.12@4250,1900
  Solder Side w6: v1(3020,1665) 3070,1665 3206,1529 3206,1522.13 3217.13,1511 3232.87,1511 3244,1522.13 3244,1586 v1(3165,1665)
PE4: J1A.3 U1.123 | length 2423.5
  Component Side w6: U1.123@3123.15,1295.35 3167.35,1295.35 3197,1325 3197,1726 3220,1749 v1(3220,1980) ; v1(3140,2030) 3200,2090 4560,2090 J1A.3@4650,2000
  Solder Side w6: v1(3140,2030) 3190,1980 v1(3220,1980)
PE5: J1A.11 U1.124 | length 1756.6
  Component Side w6: U1.124@3123.15,1311.1 3159,1311.1 3186,1338.1 3186,1926 v1(3195,1935)
  Solder Side w6: v1(3195,1935) 3211.48,1951.48 4201.48,1951.48 J1A.11@4250,2000
PF1: J1B.1 U1.43 | length 3101.2
  Component Side w6: v1(2413,1194) 2435.61,1216.61 U1.43@2516.85,1216.61 ; v1(3180,1110) 3275,1110 3305,1080 v1(3305,899) ; v1(4110,670) 4520,670 4640,550 4640,420 4750,310 J1B.1@4750,300
  Solder Side w6: v1(2413,1194) 2427,1208 2465,1208 2489.51,1183.49 2711.51,1183.49 2725,1170 2803,1170 2843,1210 2930,1210 2940.61,1199.39 2940.61,1130.39 2970,1101 3031,1101 3040,1110 v1(3180,1110) ; v1(3305,899) 3534,670 v1(4110,670)
PF2: J1B.3 U1.44 | length 2961.8
  Component Side w6: U1.44@2516.85,1200.87 2580.87,1200.87 2595,1215 v1(2595,1240) ; v1(2945,905) 2945,939.5 2955.5,950 2955.5,1125.5 v1(2970,1140)
  Solder Side w6: v1(2595,1240) 2677.44,1240 2695.44,1222 2953.56,1222 2970,1205.56 v1(2970,1140) ; v1(2945,905) 2945,884 3702.5,126.5 4546.5,126.5 4600,180 4600,250 J1B.3@4650,300
PF3: J1B.5 U1.45 | length 5683.5
  Component Side w6: v1(2447,1189) 2450.88,1185.12 U1.45@2516.85,1185.12
  Solder Side w6: v1(2447,1189) 2374,1116 1960.44,1116 1919,1074.56 1919,1061 1918,1060 1918,638 1860,580 1460,580 1400,520 1400,190 1500,90 4601.48,90 4701.48,190 4701.48,308.52 4660,350 4658,348 4580,348 4550,318 J1B.5@4550,300
PG0: J1B.7 U1.49 | length 3087.4
  Component Side w6: U1.49@2516.85,1122.13 2582.87,1122.13 v1(2600,1105) ; v1(2580,670) 2580,160 2610,130 4240.48,130 4290.48,180 4290.48,230.48 4320,260 4332.75,260 4333.23,259.52 4366.77,259.52 4367.25,260 4410,260 J1B.7@4450,300
  Solder Side w6: v1(2580,670) 2580,747 2673,840 2673,1033 2665,1041 2664,1041 v1(2600,1105)
PG1: J2B.1 U1.50 | length 1125.3
  Component Side w6: v1(2314,430) v1(2314,720) ; U1.50@2516.85,1106.38 2563.62,1106.38 v1(2600,1070)
  Solder Side w6: J2B.1@2250,300 2314,364 v1(2314,430) ; v1(2314,720) 2314,761 2471,918 2620,918 2630,928 2630,1040 v1(2600,1070)
PH0: J2B.13 U1.29 | length 1938.7
  Component Side w6: J2B.13@1650,300 1650,560 1710,620 v1(2230,620) ; U1.29@2623.15,1433.15 2623.15,1361.05 2654.65,1329.56 2654.65,925.65 v1(2654,925)
  Solder Side w6: v1(2230,620) 2305,620 2575,890 2620,890 2655,925 v1(2654,925)
PH1: J2B.15 U1.30 | length 2047
  Component Side w6: J2B.15@1550,300 1550,610 1590,650 v1(2260,650) ; v1(2370,720) 2397,720 2595.92,918.92 2620,918.92 2643,941.92 2643,1167.31 2643.65,1167.95 2643.65,1325 2607.4,1361.24 U1.30@2607.4,1433.15
  Solder Side w6: v1(2260,650) 2300,650 v1(2370,720)
PH2: J1B.6 U1.31 | length 3383.1
  Component Side w6: U1.31@2591.65,1433.15 2591.65,1664.78 v1(2676.94,1750.06) ; v1(4360,590) 4479.52,590 4509.52,560 4509.52,282.75 4510,282.27 4510,240 J1B.6@4550,200
  Solder Side w6: v1(2676.94,1750.06) 2710,1717 3769.51,1717 3960.48,1526.03 3960.48,965.07 4335.56,590 v1(4360,590)
PH3: J1B.8 U1.32 | length 3563.7
  Component Side w6: U1.32@2575.91,1433.15 2575.91,1703.5 v1(2626,1753.59)
  Solder Side w6: v1(2626,1753.59) 2652.47,1780.06 2728.21,1780.06 2777.28,1731 2980,1731 2981,1730 3432.43,1730 3433.43,1731 3771.07,1731 3971.48,1530.59 3971.48,969.63 4111.11,830 4451,830 4491,790 4491,241 J1B.8@4450,200
PK0: J2A.10 U1.18 | length 1394.5
  Component Side w6: v1(1850,1580) J2A.10@1850,1900 ; U1.18@2796.38,1433.15 2796.38,1486.38 v1(2805,1495)
  Solder Side w6: v1(1850,1580) 2752.25,1580 2805,1527.25 v1(2805,1495)
PK1: J2A.12 U1.19 | length 1770.1
  Component Side w6: v1(1800,2070) 2710,2070 2759,2021 2759,1787.39 2784.54,1761.85 2784.54,1655.51 2780.63,1651.6 U1.19@2780.63,1433.15
  Solder Side w6: J2A.12@1750,1900 1800,1950 v1(1800,2070)
PK2: J2A.14 U1.20 | length 1559.5
  Component Side w6: v1(1650,1660) J2A.14@1650,1900 ; v1(2758,1629) 2764.88,1622.12 U1.20@2764.88,1433.15
  Solder Side w6: v1(1650,1660) 1659,1651 2736,1651 v1(2758,1629)
PK3: J2A.16 U1.21 | length 1624.1
  Component Side w6: v1(1550,1680) J2A.16@1550,1900 ; v1(2730.13,1627.5) 2749.13,1608.5 U1.21@2749.13,1433.15
  Solder Side w6: v1(1550,1680) 1590,1640 2717.63,1640 v1(2730.13,1627.5)
PK4: J2B.3 U1.63 | length 842.5
  Component Side w6: J2B.3@2150,300 2150,320 2190,360 2290,360 2333.24,403.24 2333.24,769.83 2465.06,901.65 U1.63@2516.85,901.65
PK5: J2B.5 U1.62 | length 964.7
  Component Side w6: J2B.5@2050,300 v1(2050,510) ; v1(2050,575) 2062.5,587.5 2272.5,587.5 2295,610 2295,748.33 2464.07,917.4 U1.62@2516.85,917.4
  Solder Side w6: v1(2050,510) v1(2050,575)
PK6: J2B.17 U1.61 | length 1528.3
  Component Side w6: J2B.17@1450,300 1450,640 1480,670 2201.11,670 2464.26,933.15 U1.61@2516.85,933.15
PK7: J2B.19 U1.60 | length 1623.1
  Component Side w6: J2B.19@1350,300 1350,620 1420,690 2205.56,690 2464.45,948.9 U1.60@2516.85,948.9
PL0: J1B.13 U1.81 | length 1759.2
  Component Side w6: v1(2827.87,715) U1.81@2827.87,826.85 ; v1(3165,580) 4090,580 4150,520 J1B.13@4150,300
  Solder Side w6: v1(2827.87,715) 2827.87,673.31 2921.18,580 v1(3165,580)
PL1: J1B.15 U1.82 | length 1685.6
  Component Side w6: U1.82@2843.62,826.85 2843.62,731.38 v1(2895,680) ; v1(3115,680) 4020,680 v1(4050,650)
  Solder Side w6: v1(2895,680) v1(3115,680) ; J1B.15@4050,300 v1(4050,650)
PL2: J1B.17 U1.83 | length 1391.6
  Component Side w6: U1.83@2859.37,826.85 2859.37,745.63 v1(2870,735) ; v1(3335,445) v1(3735,445)
  Solder Side w6: v1(2870,735) 2870,675 2945,600 3180,600 v1(3335,445) ; v1(3735,445) 3805,445 J1B.17@3950,300
PL3: J1B.19 U1.84 | length 1261.6
  Component Side w6: U1.84@2875.12,826.85 2875.12,770 v1(2895,750.12) ; v1(2970,705) 2970,645 2995,620 3088,620 3408,300 J1B.19@3850,300
  Solder Side w6: v1(2895,750.12) 2940.12,705 v1(2970,705)
PL4: J1B.9 U1.85 | length 2206.7
  Component Side w6: v1(2890,1035) 2871.5,1016.5 2871.5,903 2890.87,883.63 U1.85@2890.87,826.85
  Solder Side w6: v1(2890,1035) 2904,1049 3066,1049 3140.85,974.15 3308.15,974.15 3374,1040 3870,1040 4320,590 4320,330 J1B.9@4350,300
PL5: J1B.11 U1.86 | length 1899.1
  Component Side w6: v1(2895,965) 2906.61,953.39 U1.86@2906.61,826.85 ; v1(3580,630) 4070,630 v1(4080,620)
  Solder Side w6: v1(2895,965) 2895,980 2915,1000 3046.81,1000 3160.31,886.5 3260.37,886.5 3516.87,630 v1(3580,630) ; v1(4080,620) 4250,450 J1B.11@4250,300
PM0: J2B.20 U1.78 | length 2728.8
  Component Side w6: v1(1329,580) 1309,560 1309,241 J2B.20@1350,200 ; v1(2740,1195) 2780.63,1154.37 U1.78@2780.63,826.85
  Solder Side w6: v1(1329,580) 1340,591 1851,591 1900,640 1900,1070 1908,1078 1908,1079.11 1955.89,1127 1957,1127 2049,1219 2477,1219 2501.51,1194.49 2739.49,1194.49 v1(2740,1195)
PM3: J1B.4 U1.75 | length 2739.7
  Component Side w6: U1.75@2733.39,826.85 2733.39,753.39 2700,720 2700,490 2640,430 2640,210 2680,170 v1(2855.56,170)
  Solder Side w6: v1(2855.56,170) 2910.06,115.5 4565.5,115.5 J1B.4@4650,200
PM4: J1A.18 U1.74 | length 2117.2
  Component Side w6: U1.74@2717.64,826.85 2717.64,866.64 2730,879 v1(2730,895) ; v1(3680,1060) 3680,1220 3950,1490 v1(3950,1680)
  Solder Side w6: v1(2730,895) 2730,915 2875,1060 3080,1060 3154.85,985.15 3295.15,985.15 3370,1060 v1(3680,1060) ; v1(3950,1680) J1A.18@3950,1900
PM5: J1A.20 U1.73 | length 2137.9
  Component Side w6: U1.73@2701.89,826.85 2701.89,1021.89 v1(2730,1050) ; v1(3850,1500) v1(3850,1700)
  Solder Side w6: v1(2730,1050) 2800,1120 2925,1120 2955,1090 3090,1090 3172.85,1007.15 3275,1007.15 3310,1042.15 3310,1218.35 3331.65,1240 3521.65,1430 3780,1430 v1(3850,1500) ; v1(3850,1700) J1A.20@3850,1900
PM7: J2B.4 U1.71 | length 1102
  Component Side w6: J2B.4@2150,200 2200,250 2330,250 2380,300 2380,687.44 2597.56,905 2643.89,905 2670.39,878.5 U1.71@2670.39,826.85
PN2: J1B.16 U1.109 | length 1725.6
  Component Side w6: v1(2974.5,900) 2974.5,1042 3007.38,1074.88 U1.109@3123.15,1074.88
  Solder Side w6: v1(2974.5,900) 2974.5,893 3730,137.5 3987.5,137.5 J1B.16@4050,200
PN3: J1B.18 U1.110 | length 1623.6
  Component Side w6: U1.110@3123.15,1090.63 3274.37,1090.63 3286.92,1078.08 3286.92,1035 3260,1008.08 v1(3260,910)
  Solder Side w6: v1(3260,910) 3520,650 3940,650 3990,600 3990,410.48 3990.48,410 3990.48,283.23 3950,242.75 J1B.18@3950,200
PN4: J2A.19 U1.111 | length 2869.5
  Component Side w6: v1(2990,1120) 3003.62,1106.38 U1.111@3123.15,1106.38
  Solder Side w6: J2A.19@1350,2000 1285,2000 1250,1965 1250,1734 1374,1610 1860,1610 1879,1591 2757,1591 2786,1620 2848,1620 2890,1578 2890,1456 2891,1455 3005.04,1455 3099,1361.04 3099,1310 2990,1201 v1(2990,1120)
PN5: J2A.17 U1.112 | length 2551.4
  Component Side w6: J2A.17@1450,2000 1500,1950 1680,1950 1704.5,1925.5 v1(1704.5,1716) ; v1(3020,1130) 3027.87,1122.13 U1.112@3123.15,1122.13
  Solder Side w6: v1(1704.5,1716) 1736.5,1684 2926,1684 2948,1662 2948,1487 2949,1486 3015.1,1486 3121,1380.1 3121,1261 3020,1160 v1(3020,1130)
POE_NET01: J6.9 J11.1 | length 1044.4
  Component Side w25: J11.1@330,1550 330,1097.43 672.43,755 J6.9@780,755
POE_NET02: J6.10 J10.2 | length 1154.6
  Component Side w25: J10.2@180,1550 180,1030 296.21,913.79 471.21,913.79 J6.10@680,705
POE_NET03: D6.2 J7.2 R31.2 | length 917.6
  Component Side w25: D6.2@330,2158.74 330,2290 170,2450 J7.2@170,2671.1 507.4,2671.1 R31.2@508.5,2670
POE_NET04: C33.1 C42.1 D5.1 FB1.2 L1.1 R35.2 U3.8 U3.9 | length 2742.9
  Component Side w25: FB1.2@450,1880 510,1880 580,1950 580,2278.74 D5.1@578.74,2280 1130,2280 1260,2410 1260,2666 ; C33.1@760,2580 828.5,2580 ; R35.2@828.5,2450 828.5,2580 ; U3.9@908.05,2583.86 U3.8@883.23,2583.86 879.37,2580 828.5,2580 ; L1.1@1632.52,2810 1519.3,2810 1513,2803.7 C42.1@1400,2803.7 1400,2700 1366,2666 1260,2666 ; 828.5,2580 828.5,2618.5 876,2666 1260,2666
POE_NET05: C30.2 C40.1 C41.1 C53.1 L1.2 R52.2 T1.3 | length 1663.3
  Component Side w25: L1.2@1847.48,2810 2053.23,2810 C40.1@2060,2816.77 C41.1@2210,2816.77 2358.23,2816.77 T1.3@2365,2810 2478,2810 2621.26,2953.26 C30.2@2621.26,3320 2611.26,3330 2490,3330 2490,3360 2475,3375 2255,3375 2240,3360 R52.2@2240,3330
POE_NET06: Q1.2 R39.2 R40.1 | length 350.1
  Component Side w25: R40.1@1877.09,3060 1881.5,3055.59 R39.2@1881.5,2960 2119.29,2960 Q1.2@2126.69,2952.6
POE_NET07: R42.2 T1.1 | length 74.6
  Component Side w25: R42.2@2361.5,2540 2365,2543.5 T1.1@2365,2613.15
